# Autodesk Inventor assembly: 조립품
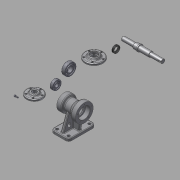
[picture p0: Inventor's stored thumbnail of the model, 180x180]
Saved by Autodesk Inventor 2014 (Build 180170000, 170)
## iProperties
Created: 2015-08
Part Number: 조립품
Document SubType Name: Assembly
Designer: USER
Author: USER
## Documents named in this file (10)
- C:\Users\USER\Desktop\450805V1009\조립품.iam
- C:\Users\USER\Desktop\450805V1009\본체.ipt
- C:\Users\USER\Desktop\450805V1009\M4x0.5.ipt
- C:\Users\USER\Desktop\450805V1009\뒤커버.ipt
- C:\Users\USER\Desktop\450805V1009\베어링 6203.ipt
- C:\Users\USER\Desktop\450805V1009\베어링 6205.ipt
- C:\Users\USER\Desktop\450805V1009\앞커버.ipt
- C:\Users\USER\Desktop\450805V1009\오일실 .ipt
- 오일실 .ipt
- C:\Users\USER\Desktop\450805V1009\축.ipt
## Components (1 placed, 1 different names)
1. M4x0.5:1
